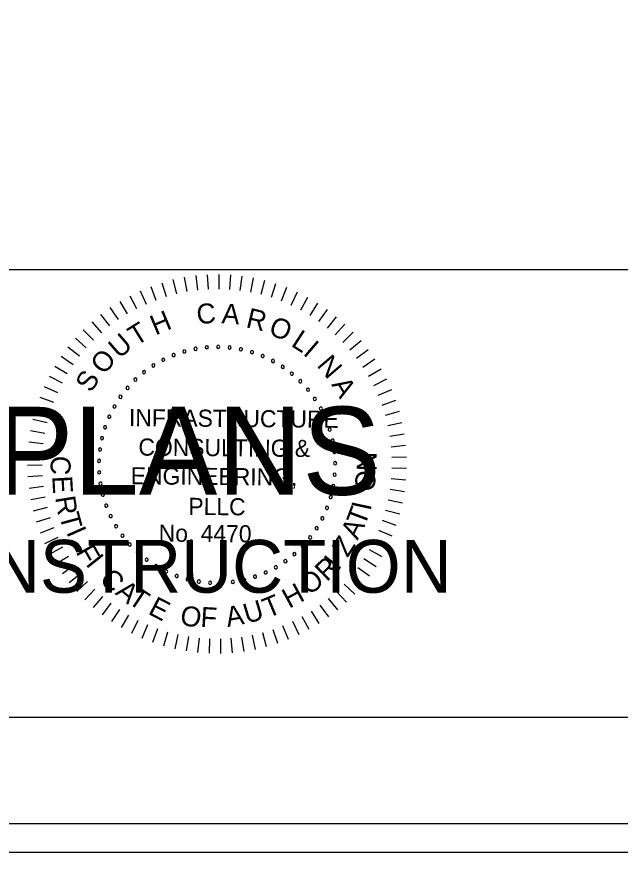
# Model space of a CAD drawing. Extents: x 967 to 1746, y 964 to 7904.
# Drawn here: x 1189.3 to 1212.88, y 4323.72 to 4356.36 of the extents above; entities that cross this region are included whole.
import ezdxf

# ---------------------------------------------------------------- set-up
doc = ezdxf.new("R2010")
doc.units = 0
for name, color, linetype in [('RD_SHT_Bndy', 7, 'Continuous'), ('RD_SHT_IplotShp', 7, 'Continuous'), ('RD_SHT_Misc1', 7, 'Continuous'), ('RD_SHT_Misc2', 7, 'Continuous'), ('RD_Sketch1', 7, 'Continuous')]:
    doc.layers.add(name, color=color, linetype=linetype)

msp = doc.modelspace()

# ---------------------------------------------------------------- linework, layer by layer
at = {"layer": 'RD_SHT_Bndy'}
for p, q in [((996.114, 4346.486), (1323.886, 4346.486)), ((1323.886, 4328.983), (996.114, 4328.983))]:
    msp.add_line(p, q, dxfattribs=at)
at = {"layer": 'RD_SHT_IplotShp'}
for points in [[(967.409, 4323.72), (1326.285, 4323.72), (1326.285, 4543.72), (967.409, 4543.72)], [(988.525, 4324.84), (1326.285, 4324.84), (1326.285, 4542.6), (988.525, 4542.6)]]:
    msp.add_lwpolyline(points, close=True, dxfattribs=at)
at = {"layer": 'RD_SHT_Misc1'}
for p, q in [((1195.403, 4346.09), (1195.536, 4345.536)), ((1195.846, 4346.181), (1195.945, 4345.62)), ((1196.292, 4346.245), (1196.357, 4345.68)), ((1196.742, 4346.282), (1196.772, 4345.714)), ((1197.194, 4346.292), (1197.189, 4345.723)), ((1197.645, 4346.274), (1197.606, 4345.706)), ((1198.094, 4346.228), (1198.02, 4345.664)), ((1198.54, 4346.156), (1198.432, 4345.596)), ((1198.98, 4346.056), (1198.838, 4345.504)), ((1194.54, 4345.827), (1194.739, 4345.293)), ((1194.968, 4345.971), (1195.134, 4345.427)), ((1199.414, 4345.929), (1199.238, 4345.387)), ((1199.839, 4345.777), (1199.63, 4345.246)), ((1193.715, 4345.461), (1193.978, 4344.956)), ((1194.122, 4345.656), (1194.353, 4345.136)), ((1200.253, 4345.598), (1200.013, 4345.082)), ((1200.656, 4345.395), (1200.385, 4344.894)), ((1193.321, 4345.241), (1193.614, 4344.752)), ((1201.047, 4345.167), (1200.745, 4344.684)), ((1192.576, 4344.731), (1192.926, 4344.282)), ((1192.94, 4344.997), (1193.263, 4344.528)), ((1201.422, 4344.917), (1201.092, 4344.453)), ((1192.228, 4344.443), (1192.605, 4344.016)), ((1201.781, 4344.643), (1201.424, 4344.2)), ((1191.899, 4344.134), (1192.301, 4343.731)), ((1202.124, 4344.349), (1201.739, 4343.928)), ((1202.447, 4344.034), (1202.038, 4343.638)), ((1191.589, 4343.805), (1192.015, 4343.428)), ((1202.751, 4343.7), (1202.318, 4343.329)), ((1191.299, 4343.459), (1191.748, 4343.108)), ((1191.032, 4343.095), (1191.501, 4342.772)), ((1203.034, 4343.348), (1202.579, 4343.004)), ((1203.294, 4342.979), (1202.82, 4342.664)), ((1190.787, 4342.716), (1191.274, 4342.422)), ((1203.532, 4342.595), (1203.04, 4342.31)), ((1190.565, 4342.323), (1191.07, 4342.059)), ((1203.746, 4342.198), (1203.237, 4341.943)), ((1190.368, 4341.916), (1190.888, 4341.684)), ((1203.936, 4341.788), (1203.412, 4341.564)), ((1190.196, 4341.499), (1190.729, 4341.299)), ((1204.1, 4341.367), (1203.563, 4341.176)), ((1190.05, 4341.072), (1190.594, 4340.905)), ((1204.238, 4340.937), (1203.691, 4340.779)), ((1189.93, 4340.636), (1190.484, 4340.503)), ((1204.349, 4340.5), (1203.794, 4340.375)), ((1189.837, 4340.195), (1190.398, 4340.095)), ((1204.434, 4340.056), (1203.872, 4339.966)), ((1189.771, 4339.748), (1190.337, 4339.683)), ((1204.491, 4339.608), (1203.925, 4339.552)), ((1189.732, 4339.298), (1190.301, 4339.267)), ((1204.522, 4339.158), (1203.953, 4339.137)), ((1189.721, 4338.847), (1190.29, 4338.851)), ((1204.524, 4338.706), (1203.955, 4338.72)), ((1189.737, 4338.396), (1190.306, 4338.434)), ((1204.499, 4338.256), (1203.932, 4338.304)), ((1189.781, 4337.946), (1190.346, 4338.019)), ((1204.447, 4337.807), (1203.884, 4337.89)), ((1189.852, 4337.5), (1190.412, 4337.608)), ((1189.951, 4337.06), (1190.502, 4337.201)), ((1204.367, 4337.363), (1203.81, 4337.479)), ((1204.261, 4336.924), (1203.712, 4337.074)), ((1190.076, 4336.626), (1190.617, 4336.8)), ((1204.128, 4336.492), (1203.589, 4336.676)), ((1190.227, 4336.2), (1190.757, 4336.408)), ((1203.969, 4336.07), (1203.442, 4336.286)), ((1190.403, 4335.785), (1190.92, 4336.024)), ((1203.784, 4335.658), (1203.271, 4335.906)), ((1190.605, 4335.381), (1191.106, 4335.651)), ((1190.831, 4334.99), (1191.315, 4335.291)), ((1203.574, 4335.258), (1203.078, 4335.537)), ((1191.081, 4334.614), (1191.545, 4334.943)), ((1203.341, 4334.871), (1202.862, 4335.18)), ((1191.353, 4334.253), (1191.796, 4334.61)), ((1203.085, 4334.5), (1202.626, 4334.837)), ((1191.646, 4333.91), (1192.067, 4334.293)), ((1202.806, 4334.145), (1202.368, 4334.509)), ((1191.96, 4333.585), (1192.356, 4333.994)), ((1202.506, 4333.807), (1202.092, 4334.197)), ((1192.293, 4333.28), (1192.664, 4333.712)), ((1201.847, 4333.19), (1201.484, 4333.628)), ((1202.186, 4333.488), (1201.796, 4333.903)), ((1192.644, 4332.996), (1192.988, 4333.45)), ((1201.491, 4332.912), (1201.155, 4333.372)), ((1193.011, 4332.734), (1193.327, 4333.208)), ((1193.394, 4332.495), (1193.68, 4332.987)), ((1201.119, 4332.657), (1200.811, 4333.136)), ((1193.791, 4332.279), (1194.047, 4332.788)), ((1194.2, 4332.088), (1194.424, 4332.612)), ((1200.331, 4332.217), (1200.083, 4332.73)), ((1200.731, 4332.425), (1200.453, 4332.922)), ((1194.62, 4331.923), (1194.812, 4332.459)), ((1195.05, 4331.783), (1195.208, 4332.33)), ((1199.063, 4331.745), (1198.913, 4332.295)), ((1199.495, 4331.877), (1199.312, 4332.416)), ((1199.918, 4332.034), (1199.702, 4332.561)), ((1195.487, 4331.67), (1195.612, 4332.225)), ((1195.93, 4331.584), (1196.021, 4332.146)), ((1196.377, 4331.524), (1196.434, 4332.091)), ((1196.828, 4331.493), (1196.85, 4332.062)), ((1197.279, 4331.488), (1197.267, 4332.058)), ((1197.73, 4331.512), (1197.683, 4332.079)), ((1198.179, 4331.562), (1198.097, 4332.126)), ((1198.624, 4331.64), (1198.508, 4332.198))]:
    msp.add_line(p, q, dxfattribs=at)
for centre, start, end in [((1196.285, 4343.388), 10.6038, 190.6038), ((1196.285, 4343.388), 190.6038, 10.6038), ((1196.727, 4343.447), 5.0653, 185.0653), ((1196.727, 4343.447), 185.0653, 5.0653), ((1197.172, 4343.464), 359.5268, 179.5268), ((1197.172, 4343.464), 179.5268, 359.5268), ((1197.617, 4343.438), 173.9884, 353.9884), ((1197.617, 4343.438), 353.9884, 173.9884), ((1198.057, 4343.369), 168.4499, 348.4499), ((1198.057, 4343.369), 348.4499, 168.4499), ((1195.429, 4343.142), 21.6807, 201.6807), ((1195.429, 4343.142), 201.6807, 21.6807), ((1195.851, 4343.285), 16.1422, 196.1422), ((1195.851, 4343.285), 196.1422, 16.1422), ((1198.489, 4343.258), 162.9114, 342.9114), ((1198.489, 4343.258), 342.9114, 162.9114), ((1198.908, 4343.106), 157.373, 337.373), ((1198.908, 4343.106), 337.373, 157.373), ((1194.637, 4342.736), 32.7576, 212.7576), ((1194.637, 4342.736), 212.7576, 32.7576), ((1195.023, 4342.958), 27.2191, 207.2191), ((1195.023, 4342.958), 207.2191, 27.2191), ((1199.31, 4342.914), 151.8345, 331.8345), ((1199.31, 4342.914), 331.8345, 151.8345), ((1199.692, 4342.684), 326.2961, 146.2961), ((1194.274, 4342.478), 38.2961, 218.2961), ((1194.274, 4342.478), 218.2961, 38.2961), ((1199.692, 4342.684), 146.2961, 326.2961), ((1200.05, 4342.419), 140.7576, 320.7576), ((1200.05, 4342.419), 320.7576, 140.7576), ((1193.937, 4342.186), 43.8345, 223.8345), ((1193.937, 4342.186), 223.8345, 43.8345), ((1200.38, 4342.12), 135.2191, 315.2191), ((1200.38, 4342.12), 315.2191, 135.2191), ((1193.63, 4341.862), 49.373, 229.373), ((1193.63, 4341.862), 229.373, 49.373), ((1200.68, 4341.79), 129.6807, 309.6807), ((1200.68, 4341.79), 309.6807, 129.6807), ((1193.356, 4341.511), 54.9114, 234.9114), ((1193.356, 4341.511), 234.9114, 54.9114), ((1200.947, 4341.433), 124.1422, 304.1422), ((1200.947, 4341.433), 304.1422, 124.1422), ((1193.117, 4341.135), 60.4499, 240.4499), ((1193.117, 4341.135), 240.4499, 60.4499), ((1201.179, 4341.052), 118.6038, 298.6038), ((1201.179, 4341.052), 298.6038, 118.6038), ((1192.915, 4340.737), 65.9884, 245.9884), ((1192.915, 4340.737), 245.9884, 65.9884), ((1201.372, 4340.651), 113.0653, 293.0653), ((1201.372, 4340.651), 293.0653, 113.0653), ((1192.753, 4340.322), 71.5268, 251.5268), ((1192.753, 4340.322), 251.5268, 71.5268), ((1201.526, 4340.233), 107.5268, 287.5268), ((1201.526, 4340.233), 287.5268, 107.5268), ((1192.632, 4339.894), 77.0653, 257.0653), ((1192.632, 4339.894), 257.0653, 77.0653), ((1201.638, 4339.801), 101.9884, 281.9884), ((1201.638, 4339.801), 281.9884, 101.9884), ((1192.552, 4339.455), 82.6038, 262.6038), ((1192.552, 4339.455), 262.6038, 82.6038), ((1201.709, 4339.361), 96.4499, 276.4499), ((1201.709, 4339.361), 276.4499, 96.4499), ((1192.515, 4339.011), 88.1422, 268.1422), ((1192.515, 4339.011), 268.1422, 88.1422), ((1201.737, 4338.917), 90.9114, 270.9114), ((1201.737, 4338.917), 270.9114, 90.9114), ((1192.522, 4338.565), 93.6807, 273.6807), ((1192.522, 4338.565), 273.6807, 93.6807), ((1201.721, 4338.471), 85.373, 265.373), ((1201.721, 4338.471), 265.373, 85.373), ((1192.571, 4338.122), 99.2191, 279.2191), ((1192.571, 4338.122), 279.2191, 99.2191), ((1201.663, 4338.029), 79.8345, 259.8345), ((1201.663, 4338.029), 259.8345, 79.8345), ((1192.662, 4337.686), 104.7576, 284.7576), ((1192.662, 4337.686), 284.7576, 104.7576), ((1201.563, 4337.595), 74.2961, 254.2961), ((1201.563, 4337.595), 254.2961, 74.2961), ((1192.796, 4337.261), 110.2961, 290.2961), ((1192.796, 4337.261), 290.2961, 110.2961), ((1201.42, 4337.173), 68.7576, 248.7576), ((1201.42, 4337.173), 248.7576, 68.7576), ((1192.97, 4336.851), 115.8345, 295.8345), ((1192.97, 4336.851), 295.8345, 115.8345), ((1193.182, 4336.459), 301.373, 121.373), ((1201.238, 4336.766), 63.2191, 243.2191), ((1201.238, 4336.766), 243.2191, 63.2191), ((1193.182, 4336.459), 121.373, 301.373), ((1201.018, 4336.379), 57.6807, 237.6807), ((1201.018, 4336.379), 237.6807, 57.6807), ((1193.432, 4336.09), 126.9114, 306.9114), ((1193.432, 4336.09), 306.9114, 126.9114), ((1200.761, 4336.014), 52.1422, 232.1422), ((1200.761, 4336.014), 232.1422, 52.1422), ((1193.715, 4335.746), 132.4499, 312.4499), ((1193.715, 4335.746), 312.4499, 132.4499), ((1200.47, 4335.677), 46.6038, 226.6038), ((1200.47, 4335.677), 226.6038, 46.6038), ((1194.031, 4335.431), 137.9884, 317.9884), ((1194.031, 4335.431), 317.9884, 137.9884), ((1200.148, 4335.369), 41.0653, 221.0653), ((1200.148, 4335.369), 221.0653, 41.0653), ((1194.376, 4335.149), 143.5268, 323.5268), ((1194.376, 4335.149), 323.5268, 143.5268), ((1194.746, 4334.901), 149.0653, 329.0653), ((1194.746, 4334.901), 329.0653, 149.0653), ((1199.422, 4334.853), 29.9884, 209.9884), ((1199.798, 4335.093), 35.5268, 215.5268), ((1199.798, 4335.093), 215.5268, 35.5268), ((1195.139, 4334.69), 154.6038, 334.6038), ((1195.139, 4334.69), 334.6038, 154.6038), ((1195.55, 4334.517), 340.1422, 160.1422), ((1199.026, 4334.65), 24.4499, 204.4499), ((1199.026, 4334.65), 204.4499, 24.4499), ((1199.422, 4334.853), 209.9884, 29.9884), ((1195.55, 4334.517), 160.1422, 340.1422), ((1195.975, 4334.386), 165.6807, 345.6807), ((1195.975, 4334.386), 345.6807, 165.6807), ((1196.412, 4334.295), 171.2191, 351.2191), ((1196.412, 4334.295), 351.2191, 171.2191), ((1196.855, 4334.248), 356.7576, 176.7576), ((1196.855, 4334.248), 176.7576, 356.7576), ((1197.301, 4334.243), 2.2961, 182.2961), ((1197.301, 4334.243), 182.2961, 2.2961), ((1197.745, 4334.282), 7.8345, 187.8345), ((1197.745, 4334.282), 187.8345, 7.8345), ((1198.183, 4334.363), 13.373, 193.373), ((1198.183, 4334.363), 193.373, 13.373), ((1198.611, 4334.486), 18.9114, 198.9114), ((1198.611, 4334.486), 198.9114, 18.9114)]:
    msp.add_arc(centre, 0.0627, start, end, dxfattribs=at)
at = {"layer": 'RD_Sketch1'}
msp.add_lwpolyline([(967.409, 4323.72), (1326.285, 4323.72), (1326.285, 4543.72), (967.409, 4543.72)], close=True, dxfattribs=at)

# ---------------------------------------------------------------- texts
at = {"layer": 'RD_SHT_Misc1'}
for s, height, rotation, p in [('C', 0.78, 4.7281, (1196.355, 4344.346)), ('A', 0.78, 355.6981, (1197.29, 4344.39)), ('H', 0.78, 22.7882, (1194.72, 4343.904)), ('R', 0.78, 346.6681, (1198.222, 4344.238)), ('T', 0.78, 31.8182, (1193.961, 4343.478)), ('O', 0.78, 337.638, (1199.096, 4343.972)), ('L', 0.78, 327.108, (1199.981, 4343.52)), ('U', 0.78, 40.8482, (1193.306, 4342.976)), ('I', 0.78, 319.578, (1200.451, 4343.182)), ('O', 0.78, 49.8782, (1192.707, 4342.341)), ('N', 0.78, 310.548, (1200.994, 4342.728)), ('S', 0.78, 58.9083, (1192.211, 4341.642)), ('A', 0.78, 301.5179, (1201.576, 4341.991)), ('INFRASTRUCTURE', 0.66873, 359.5268, (1193.682, 4340.367)), ('CONSULTING &', 0.66873, 359.5268, (1194.051, 4339.217)), ('C', 0.78, 267.025, (1190.646, 4339.227)), ('N', 0.78, 89.2085, (1203.359, 4338.604)), ('ENGINEERING,', 0.66873, 359.5268, (1193.751, 4338.095)), ('O', 0.78, 83.2085, (1203.26, 4337.786)), ('E', 0.78, 273.025, (1190.685, 4338.408)), ('R', 0.78, 279.025, (1190.799, 4337.583)), ('PLLC', 0.6687, 359.5268, (1196.002, 4336.9)), ('T', 0.78, 69.3954, (1202.891, 4336.428)), ('I', 0.78, 77.9093, (1203.121, 4337.032)), ('T', 0.78, 285.025, (1190.955, 4336.878)), ('No. 4470', 0.6687, 359.5268, (1194.843, 4335.855)), ('A', 0.78, 63.3954, (1202.616, 4335.888)), ('I', 0.78, 293.7713, (1191.221, 4336.225)), ('Z', 0.78, 57.3954, (1202.224, 4335.206)), ('F', 0.78, 299.7713, (1191.589, 4335.455)), ('I', 0.78, 308.5268, (1191.965, 4334.973)), ('R', 0.78, 44.5268, (1201.415, 4334.267)), ('I', 0.78, 52.3339, (1201.856, 4334.69)), ('C', 0.78, 314.5268, (1192.496, 4334.346)), ('O', 0.78, 38.5268, (1200.73, 4333.731)), ('A', 0.78, 320.5268, (1193.115, 4333.822)), ('H', 0.78, 28.5268, (1199.942, 4333.23)), ('T', 0.78, 326.5268, (1193.602, 4333.478)), ('E', 0.78, 332.5268, (1194.394, 4333.051)), ('T', 0.78, 22.5268, (1199.108, 4332.856)), ('O', 0.78, 350.5268, (1195.647, 4332.614)), ('F', 0.78, 356.5268, (1196.465, 4332.532)), ('A', 0.78, 10.5268, (1197.537, 4332.517)), ('U', 0.78, 16.5268, (1198.288, 4332.638))]:
    msp.add_text(s, height=height, rotation=rotation, dxfattribs=at).set_placement(p)
at = {"layer": 'RD_SHT_Misc2'}
for s, height, p in [('FINAL PLANS', 3.4375, (1174.145, 4337.685)), ('NOT FOR CONSTRUCTION', 2.0625, (1170.901, 4333.86))]:
    msp.add_text(s, height=height, dxfattribs=at).set_placement(p)

doc.saveas('drawing.dxf')
